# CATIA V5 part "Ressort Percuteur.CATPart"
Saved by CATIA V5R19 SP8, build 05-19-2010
Part number: Ressort Percuteur
Bounding box of the stored display mesh (mm): x -2.899 to 2.9, y -0.4 to 33.395, z -2.898 to 2.9
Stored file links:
  C:\Users\Arthur\Desktop\Catia parts\GLOCK\Ensemble culasse\Ressort Percuteur.CATPart
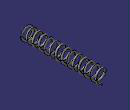
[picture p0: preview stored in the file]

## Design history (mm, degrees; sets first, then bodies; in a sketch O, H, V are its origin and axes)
Set1
  Sketch1 on xy-plane, origin (0, 0, 0), H (1, 0, 0), V (0, 1, 0)
    point P1 (2.5, 0)
    distance P1 V = 2.5
  Helix1: Direction Sketch1.V, RefPoint Sketch1, Pitch 2.5, Height 33, TaperAngle 0
  Plane1: type OffsetPt, RefPlane xy-plane, RefPoint Sketch1
  Circle1: type CtrRad, Start 0, End 180, Center Sketch1, Support xy-plane, Radius 0.4, FirstDirection (1, 0, 0)
Body1 (main body)
  Rib1: profile Circle1, centre curve Helix1
  Shaft1: profile face of Rib1, axis Sketch1.V, angle 360
  Sketch2 on xy-plane, origin (0, 0, 0), H (1, 0, 0), V (0, 1, 0)
    line L1 (0, 0) -> (0, 14.4495)
    vertical: L1 V
  Plane2: type Offset, RefPlane zx-plane, Offset 0.4, reversed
